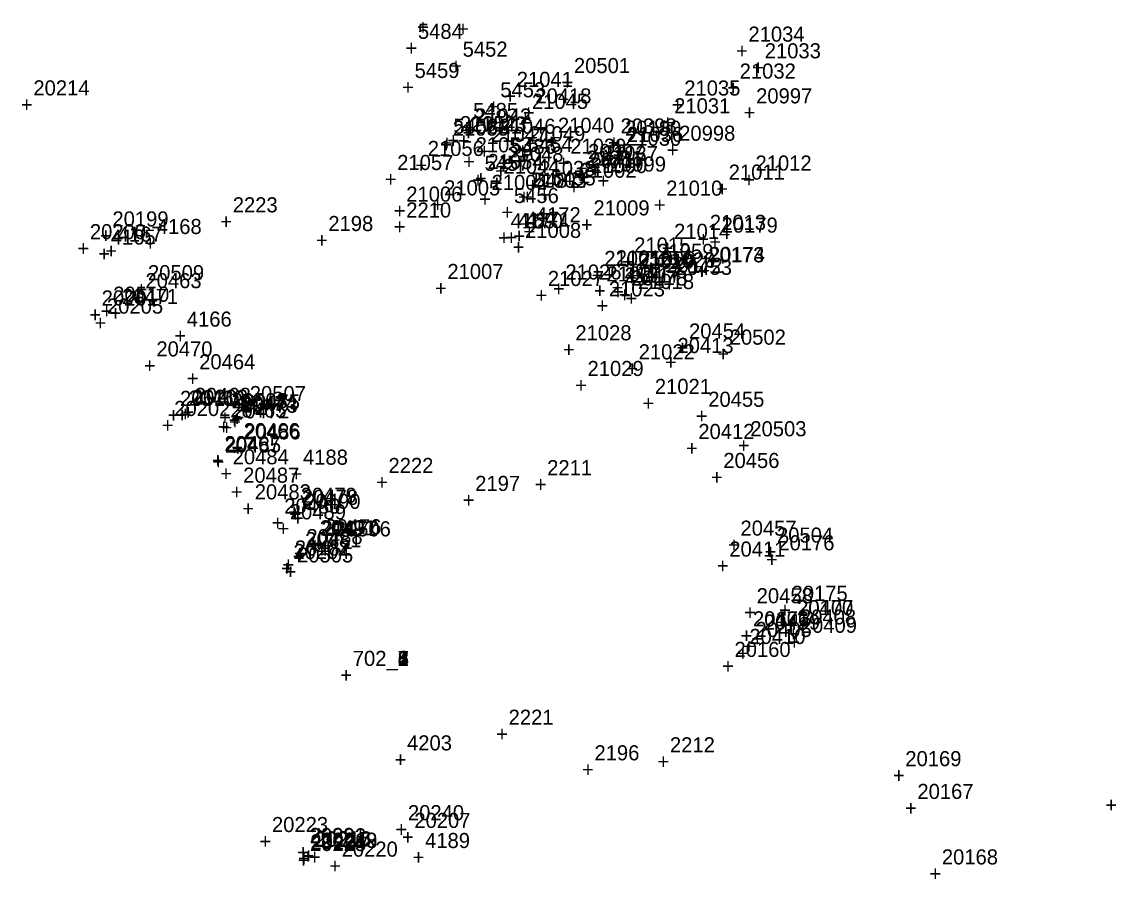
# Model space of a CAD drawing. Extents: x 1036751 to 1042192, y 772604 to 785439.
# Drawn here: x 1041377 to 1041558.2, y 774615.1 to 774757.2 of the extents above; entities that cross this region are included whole.
import ezdxf

# ---------------------------------------------------------------- set-up
doc = ezdxf.new("R2010")
doc.units = 0
for name, color, linetype in [('S_Buildings', 7, 'Continuous'), ('S_Buildings_Attachments', 7, 'Continuous'), ('S_Buildings_SillElevation', 7, 'Continuous'), ('S_Buildings_Steps_Brick', 7, 'Continuous'), ('S_Control_Temp_Traverse', 7, 'Continuous'), ('S_Drainage_CB', 7, 'Continuous'), ('S_Drainage_Culvert_Top', 7, 'Continuous'), ('S_Drainage_Invert', 7, 'Continuous'), ('S_Drainage_Sump', 7, 'Continuous'), ('S_Ground_Elevation', 7, 'Continuous'), ('S_Ground_LevelString', 7, 'Continuous'), ('S_Misc_MiscItems', 7, 'Continuous'), ('S_Property_ConcPad', 7, 'Continuous'), ('S_Property_IronPipeFound', 7, 'Continuous'), ('S_Property_Lawn', 7, 'Continuous'), ('S_Roadway_Centerline', 7, 'Continuous'), ('S_Roadway_Edge_Pavement', 7, 'Continuous'), ('S_Roadway_Edge_TW', 7, 'Continuous'), ('S_Traffic_Post_Conc', 7, 'Continuous'), ('S_Traffic_Sign_DoublePost', 7, 'Continuous'), ('S_Utilities_GuyWire3', 7, 'Continuous'), ('S_Utilities_Pole_Power', 7, 'Continuous'), ('S_Utilities_UG_Sanitary_MH', 7, 'Continuous'), ('S_Utilities_UG_Sanitary_Sewer', 7, 'Continuous'), ('S_Utilities_UG_Water_Shutoff', 7, 'Continuous')]:
    doc.layers.add(name, color=color, linetype=linetype)

msp = doc.modelspace()

# ---------------------------------------------------------------- texts
at = {"layer": 'S_Buildings'}
for s, p in [('20180', (1041476.9, 774738.29)), ('+', (1041474.84, 774735.54)), ('20174', (1041490.78, 774717.38)), ('+', (1041488.71, 774714.63)), ('20201', (1041390.22, 774710.17)), ('+', (1041388.16, 774707.42)), ('20203', (1041405.16, 774693.72)), ('20202', (1041402.24, 774691.86)), ('+', (1041403.1, 774690.97)), ('+', (1041400.17, 774689.11)), ('20204', (1041421.97, 774668.16)), ('+', (1041419.91, 774665.41)), ('20175', (1041504.47, 774661.24)), ('+', (1041502.41, 774658.49)), ('20167', (1041525.31, 774628.42)), ('+', (1041523.24, 774625.67)), ('20207', (1041442, 774623.62)), ('+', (1041439.94, 774620.87)), ('20168', (1041529.36, 774617.57)), ('+', (1041527.3, 774614.82))]:
    msp.add_text(s, height=2.5, dxfattribs=at).set_placement(p)
at = {"layer": 'S_Buildings_Attachments'}
for s, p in [('20398', (1041476.14, 774738.67)), ('+', (1041474.08, 774735.92)), ('20397', (1041470.78, 774734.43)), ('+', (1041468.72, 774731.68)), ('20463', (1041397.47, 774713.04)), ('20471', (1041393.59, 774710.43)), ('+', (1041395.4, 774710.29)), ('+', (1041391.53, 774707.68)), ('20470', (1041399.28, 774701.73)), ('+', (1041397.21, 774698.98)), ('20464', (1041406.37, 774699.6)), ('+', (1041404.31, 774696.85)), ('20469', (1041404.64, 774693.58)), ('20468', (1041405.62, 774694.03)), ('20475', (1041413.75, 774692.95)), ('20465', (1041411.52, 774691.6)), ('20472', (1041412, 774691.47)), ('20474', (1041413.3, 774692.7)), ('20473', (1041413.39, 774692.41)), ('+', (1041402.58, 774690.83)), ('+', (1041403.56, 774691.28)), ('+', (1041411.24, 774689.95)), ('+', (1041411.68, 774690.2)), ('+', (1041409.46, 774688.85)), ('+', (1041409.93, 774688.72)), ('+', (1041411.33, 774689.66)), ('20466', (1041413.74, 774688.19)), ('20486', (1041413.87, 774687.99)), ('20467', (1041410.54, 774686.04)), ('20485', (1041410.63, 774685.81)), ('+', (1041411.68, 774685.44)), ('+', (1041411.81, 774685.24)), ('20484', (1041411.91, 774683.86)), ('+', (1041408.48, 774683.29)), ('+', (1041408.57, 774683.06)), ('+', (1041409.85, 774681.11)), ('20483', (1041415.57, 774678.05)), ('20479', (1041423.18, 774677.48)), ('20478', (1041423.38, 774677.14)), ('+', (1041413.51, 774675.3)), ('20480', (1041420.46, 774675.7)), ('+', (1041421.12, 774674.74)), ('+', (1041421.32, 774674.39)), ('+', (1041418.4, 774672.95)), ('20477', (1041426.65, 774672)), ('20476', (1041427.24, 774672.27)), ('20481', (1041423.93, 774670.13)), ('20482', (1041422.21, 774668.75)), ('+', (1041424.59, 774669.25)), ('+', (1041425.18, 774669.52)), ('+', (1041421.87, 774667.38)), ('+', (1041420.15, 774666))]:
    msp.add_text(s, height=2.5, dxfattribs=at).set_placement(p)
at = {"layer": 'S_Buildings_SillElevation'}
for s, p in [('20501', (1041468.43, 774748.67)), ('+', (1041466.37, 774745.92)), ('20205', (1041391.1, 774708.82)), ('+', (1041389.04, 774706.07)), ('20502', (1041494.23, 774703.68)), ('+', (1041492.17, 774700.93)), ('20503', (1041497.64, 774688.5)), ('+', (1041495.58, 774685.75)), ('20487', (1041413.65, 774680.81)), ('+', (1041411.59, 774678.06)), ('20504', (1041502.06, 774670.89)), ('20176', (1041502.28, 774669.61)), ('+', (1041500, 774668.14)), ('+', (1041500.22, 774666.86)), ('20169', (1041523.31, 774633.85)), ('+', (1041521.25, 774631.1))]:
    msp.add_text(s, height=2.5, dxfattribs=at).set_placement(p)
at = {"layer": 'S_Buildings_Steps_Brick'}
for s, p in [('20490', (1041423.79, 774676.48)), ('20489', (1041421.38, 774674.74)), ('+', (1041421.73, 774673.73)), ('+', (1041419.32, 774671.99)), ('20491', (1041426.33, 774672.09)), ('20488', (1041424.13, 774670.63)), ('+', (1041424.27, 774669.34)), ('+', (1041422.06, 774667.88)), ('20407', (1041505.41, 774658.86)), ('20406', (1041498.09, 774657)), ('20408', (1041505.86, 774657.32)), ('20405', (1041498.51, 774655.25)), ('+', (1041503.35, 774656.11)), ('+', (1041496.03, 774654.25)), ('+', (1041503.8, 774654.57)), ('+', (1041496.45, 774652.5))]:
    msp.add_text(s, height=2.5, dxfattribs=at).set_placement(p)
at = {"layer": 'S_Control_Temp_Traverse'}
for s, p in [('702', (1041431.8, 774650.46)), ('702_7', (1041431.81, 774650.46)), ('702_6', (1041431.81, 774650.46)), ('702_5', (1041431.81, 774650.46)), ('702_4', (1041431.81, 774650.46)), ('702_3', (1041431.81, 774650.46)), ('702_2', (1041431.81, 774650.46)), ('702_1', (1041431.81, 774650.46)), ('702_8', (1041431.81, 774650.46)), ('+', (1041429.74, 774647.71)), ('+', (1041429.74, 774647.71)), ('+', (1041429.74, 774647.71)), ('+', (1041429.74, 774647.71)), ('+', (1041429.74, 774647.71)), ('+', (1041429.74, 774647.71)), ('+', (1041429.74, 774647.71)), ('+', (1041429.74, 774647.71)), ('+', (1041429.74, 774647.71))]:
    msp.add_text(s, height=2.5, dxfattribs=at).set_placement(p)
at = {"layer": 'S_Drainage_CB'}
for s, p in [('20216', (1041425.57, 774620.56)), ('+', (1041423.51, 774617.81))]:
    msp.add_text(s, height=2.5, dxfattribs=at).set_placement(p)
at = {"layer": 'S_Drainage_Culvert_Top'}
for s, p in [('20223', (1041418.42, 774622.93)), ('20222', (1041424.71, 774621.06)), ('+', (1041416.36, 774620.18)), ('20225', (1041424.72, 774619.79)), ('20219', (1041426.57, 774620.34)), ('20220', (1041429.96, 774618.86)), ('+', (1041422.65, 774618.31)), ('+', (1041424.51, 774617.59)), ('+', (1041422.66, 774617.04)), ('+', (1041427.9, 774616.11))]:
    msp.add_text(s, height=2.5, dxfattribs=at).set_placement(p)
at = {"layer": 'S_Drainage_Invert'}
for s, p in [('20221', (1041424.65, 774621.12)), ('20224', (1041424.79, 774620.08)), ('20218', (1041426.58, 774620.3)), ('+', (1041422.59, 774618.37)), ('+', (1041422.73, 774617.33)), ('+', (1041424.52, 774617.55))]:
    msp.add_text(s, height=2.5, dxfattribs=at).set_placement(p)
at = {"layer": 'S_Drainage_Sump'}
for s, p in [('20217', (1041425.46, 774620.47)), ('+', (1041423.4, 774617.72))]:
    msp.add_text(s, height=2.5, dxfattribs=at).set_placement(p)
at = {"layer": 'S_Ground_Elevation'}
for s, p in [('21034', (1041497.33, 774753.88)), ('21033', (1041500.03, 774751.12)), ('+', (1041495.27, 774751.13)), ('21032', (1041495.88, 774747.76)), ('+', (1041497.97, 774748.37)), ('20418', (1041462.03, 774743.64)), ('21035', (1041486.7, 774744.95)), ('+', (1041493.82, 774745.01)), ('21031', (1041485.03, 774742)), ('+', (1041459.97, 774740.89)), ('+', (1041484.64, 774742.2)), ('+', (1041482.97, 774739.25)), ('21030', (1041476.9, 774736.63)), ('21036', (1041477.21, 774737.28)), ('20417', (1041470.99, 774732.93)), ('21037', (1041473.04, 774734.1)), ('+', (1041474.84, 774733.88)), ('+', (1041475.15, 774734.53)), ('+', (1041468.93, 774730.18)), ('+', (1041470.98, 774731.35)), ('20509', (1041397.89, 774714.36)), ('+', (1041395.83, 774711.61)), ('20510', (1041392.12, 774710.79)), ('+', (1041390.06, 774708.04)), ('20511', (1041403.2, 774693.53)), ('20508', (1041411.73, 774693.15)), ('20507', (1041414.75, 774694.33)), ('+', (1041412.69, 774691.58)), ('+', (1041401.14, 774690.78)), ('+', (1041409.67, 774690.4)), ('20506', (1041428.81, 774671.92)), ('20505', (1041422.58, 774667.6)), ('+', (1041426.75, 774669.17)), ('+', (1041420.52, 774664.85))]:
    msp.add_text(s, height=2.5, dxfattribs=at).set_placement(p)
at = {"layer": 'S_Ground_LevelString'}
for s, p in [('+', (1041442.47, 774755.06)), ('5484', (1041442.59, 774754.34)), ('+', (1041449.09, 774754.76)), ('+', (1041440.53, 774751.59)), ('5452', (1041450, 774751.39)), ('5459', (1041442.04, 774747.86)), ('+', (1041447.94, 774748.64)), ('21041', (1041458.96, 774746.38)), ('+', (1041439.98, 774745.11)), ('5453', (1041456.23, 774744.66)), ('+', (1041456.89, 774743.63)), ('21045', (1041461.48, 774742.74)), ('5485', (1041451.74, 774741.23)), ('21042', (1041452.06, 774740.31)), ('+', (1041454.17, 774741.91)), ('21055', (1041448.37, 774738.31)), ('5458', (1041448.48, 774738.63)), ('21052', (1041449.54, 774739.05)), ('21043', (1041451.29, 774738.99)), ('21046', (1041456.09, 774738.62)), ('+', (1041459.42, 774739.99)), ('21040', (1041465.78, 774738.78)), ('+', (1041449.68, 774738.48)), ('+', (1041450, 774737.56)), ('21047', (1041454.69, 774737.26)), ('21049', (1041461.01, 774737.37)), ('21056', (1041444.22, 774734.94)), ('+', (1041446.31, 774735.56)), ('+', (1041446.42, 774735.88)), ('+', (1041447.48, 774736.3)), ('+', (1041449.23, 774736.24)), ('21053', (1041452.15, 774735.54)), ('+', (1041454.03, 774735.87)), ('5486', (1041458, 774735.29)), ('5454', (1041460.75, 774735.61)), ('+', (1041463.72, 774736.03)), ('21039', (1041467.82, 774735.31)), ('+', (1041452.63, 774734.51)), ('21054', (1041454.1, 774732.77)), ('21048', (1041457.41, 774733.99)), ('+', (1041458.95, 774734.62)), ('21057', (1041439.16, 774732.61)), ('+', (1041442.16, 774732.19)), ('+', (1041450.08, 774732.79)), ('5457', (1041453.63, 774732.48)), ('+', (1041455.94, 774732.54)), ('21044', (1041456.75, 774731.99)), ('+', (1041458.69, 774732.86)), ('21038', (1041462.7, 774731.62)), ('+', (1041465.76, 774732.56)), ('21002', (1041469.51, 774731.33)), ('21011', (1041494.06, 774731.02)), ('21012', (1041498.5, 774732.52)), ('+', (1041437.1, 774729.86)), ('+', (1041451.57, 774729.73)), ('+', (1041452.04, 774730.02)), ('21004', (1041454.79, 774729.32)), ('+', (1041455.35, 774731.24)), ('21003', (1041461.26, 774729.68)), ('5487', (1041461.78, 774729.69)), ('5455', (1041464.6, 774730.06)), ('+', (1041496.44, 774729.77)), ('21006', (1041440.66, 774727.38)), ('21005', (1041446.93, 774728.41)), ('+', (1041454.69, 774729.24)), ('+', (1041460.64, 774728.87)), ('+', (1041467.45, 774728.58)), ('21010', (1041483.71, 774728.36)), ('+', (1041492, 774728.27)), ('+', (1041452.73, 774726.57)), ('5456', (1041458.49, 774727.14)), ('+', (1041459.19, 774726.93)), ('+', (1041459.72, 774726.94)), ('+', (1041462.54, 774727.31)), ('+', (1041438.59, 774724.63)), ('+', (1041444.87, 774725.66)), ('+', (1041456.43, 774724.39)), ('21009', (1041471.66, 774725.09)), ('+', (1041481.65, 774725.61)), ('+', (1041469.6, 774722.34)), ('21008', (1041460.33, 774721.37)), ('+', (1041458.27, 774718.62)), ('21025', (1041473.46, 774716.71)), ('21058', (1041479.26, 774716.66)), ('21059', (1041482.24, 774717.89)), ('+', (1041480.18, 774715.14)), ('21007', (1041447.47, 774714.56)), ('21027', (1041464.11, 774713.4)), ('21026', (1041467.01, 774714.47)), ('+', (1041471.39, 774713.96)), ('21024', (1041473.81, 774714.15)), ('+', (1041477.2, 774713.91)), ('+', (1041445.41, 774711.81)), ('+', (1041464.94, 774711.72)), ('21023', (1041474.21, 774711.67)), ('+', (1041462.05, 774710.65)), ('+', (1041471.75, 774711.4)), ('+', (1041472.15, 774708.92)), ('21028', (1041468.67, 774704.4)), ('20413', (1041485.57, 774702.29)), ('+', (1041466.61, 774701.65)), ('21022', (1041479.15, 774701.24)), ('21029', (1041470.68, 774698.49)), ('+', (1041483.51, 774699.54)), ('+', (1041477.09, 774698.49)), ('+', (1041468.62, 774695.74)), ('21021', (1041481.83, 774695.51)), ('+', (1041479.77, 774692.76)), ('20412', (1041489.03, 774688.05)), ('+', (1041486.97, 774685.3)), ('20411', (1041494.16, 774668.57)), ('+', (1041492.1, 774665.82)), ('20409', (1041506, 774655.94)), ('20410', (1041497.48, 774654.09)), ('+', (1041503.94, 774653.19)), ('+', (1041495.42, 774651.34))]:
    msp.add_text(s, height=2.5, dxfattribs=at).set_placement(p)
at = {"layer": 'S_Misc_MiscItems'}
for s, p in [('4203', (1041440.79, 774636.46)), ('+', (1041438.73, 774633.71))]:
    msp.add_text(s, height=2.5, dxfattribs=at).set_placement(p)
at = {"layer": 'S_Property_ConcPad'}
for s, p in [('20173', (1041490.67, 774717.32)), ('20172', (1041483.75, 774715.58)), ('+', (1041488.61, 774714.57)), ('+', (1041481.69, 774712.83)), ('20170', (1041505.38, 774658.87)), ('20171', (1041498.08, 774657.01)), ('+', (1041503.32, 774656.12)), ('+', (1041496.01, 774654.26))]:
    msp.add_text(s, height=2.5, dxfattribs=at).set_placement(p)
at = {"layer": 'S_Property_IronPipeFound'}
for s, p in [('20214', (1041378.91, 774744.97)), ('+', (1041376.84, 774742.22)), ('20160', (1041495.02, 774651.95)), ('+', (1041492.96, 774649.2)), ('20240', (1041440.94, 774624.9)), ('+', (1041438.88, 774622.15))]:
    msp.add_text(s, height=2.5, dxfattribs=at).set_placement(p)
at = {"layer": 'S_Property_Lawn'}
msp.add_text('+', height=2.5, dxfattribs=at).set_placement((1041556.43, 774626.2))
at = {"layer": 'S_Roadway_Centerline'}
for s, p in [('2198', (1041427.76, 774722.5)), ('+', (1041425.7, 774719.75)), ('2197', (1041452.08, 774679.45)), ('+', (1041450.02, 774676.7)), ('2196', (1041471.83, 774634.82)), ('+', (1041469.77, 774632.07))]:
    msp.add_text(s, height=2.5, dxfattribs=at).set_placement(p)
at = {"layer": 'S_Roadway_Edge_Pavement'}
for s, p in [('20997', (1041498.6, 774743.65)), ('+', (1041496.53, 774740.9)), ('20998', (1041485.86, 774737.46)), ('21001', (1041470.51, 774733.32)), ('+', (1041483.8, 774734.71)), ('21000', (1041471.25, 774732.11)), ('20999', (1041474.38, 774732.35)), ('+', (1041468.45, 774730.57)), ('+', (1041472.32, 774729.6)), ('+', (1041469.19, 774729.36)), ('21013', (1041490.94, 774722.69)), ('21014', (1041485.02, 774721.21)), ('21015', (1041478.41, 774718.94)), ('+', (1041488.87, 774719.94)), ('21016', (1041475.36, 774716.81)), ('21020', (1041482.55, 774716.47)), ('+', (1041482.96, 774718.46)), ('+', (1041476.35, 774716.19)), ('21019', (1041479.09, 774716.26)), ('+', (1041473.3, 774714.06)), ('21017', (1041476.83, 774713.97)), ('+', (1041477.03, 774713.51)), ('21018', (1041479.03, 774712.89)), ('+', (1041480.49, 774713.72)), ('+', (1041474.77, 774711.22)), ('+', (1041476.97, 774710.14))]:
    msp.add_text(s, height=2.5, dxfattribs=at).set_placement(p)
at = {"layer": 'S_Roadway_Edge_TW'}
for s, p in [('2223', (1041411.93, 774725.6)), ('2210', (1041440.66, 774724.74)), ('+', (1041409.87, 774722.85)), ('+', (1041438.6, 774721.99)), ('2222', (1041437.72, 774682.42)), ('2211', (1041464, 774682.06)), ('+', (1041435.66, 774679.67)), ('+', (1041461.94, 774679.31)), ('2221', (1041457.61, 774640.71)), ('+', (1041455.54, 774637.96)), ('2212', (1041484.33, 774636.14)), ('+', (1041482.27, 774633.39))]:
    msp.add_text(s, height=2.5, dxfattribs=at).set_placement(p)
at = {"layer": 'S_Traffic_Post_Conc'}
for s, p in [('20453', (1041485.3, 774715.25)), ('+', (1041483.24, 774712.5)), ('20454', (1041487.49, 774704.69)), ('+', (1041485.43, 774701.94)), ('20455', (1041490.67, 774693.39)), ('+', (1041488.6, 774690.64)), ('20456', (1041493.17, 774683.25)), ('+', (1041491.11, 774680.5)), ('20457', (1041496.01, 774672.04)), ('+', (1041493.95, 774669.29)), ('20458', (1041498.69, 774660.84)), ('+', (1041496.62, 774658.09)), ('20459', (1041499.89, 774656.49)), ('+', (1041497.83, 774653.74))]:
    msp.add_text(s, height=2.5, dxfattribs=at).set_placement(p)
at = {"layer": 'S_Traffic_Sign_DoublePost'}
for s, p in [('20199', (1041392, 774723.26)), ('20200', (1041388.27, 774721.15)), ('+', (1041389.94, 774720.51)), ('+', (1041386.21, 774718.4))]:
    msp.add_text(s, height=2.5, dxfattribs=at).set_placement(p)
at = {"layer": 'S_Utilities_GuyWire3'}
for s, p in [('20179', (1041492.89, 774722.24)), ('+', (1041490.83, 774719.49))]:
    msp.add_text(s, height=2.5, dxfattribs=at).set_placement(p)
at = {"layer": 'S_Utilities_Pole_Power'}
for s, p in [('20177', (1041476.74, 774714.66)), ('20178', (1041477.9, 774713.48)), ('+', (1041474.68, 774711.91)), ('+', (1041475.84, 774710.73))]:
    msp.add_text(s, height=2.5, dxfattribs=at).set_placement(p)
at = {"layer": 'S_Utilities_UG_Sanitary_MH'}
for s, p in [('4170', (1041459.15, 774722.97)), ('4165', (1041391.72, 774720.26)), ('+', (1041457.09, 774720.22)), ('+', (1041389.66, 774717.51)), ('4166', (1041404.32, 774706.67)), ('+', (1041402.26, 774703.92))]:
    msp.add_text(s, height=2.5, dxfattribs=at).set_placement(p)
at = {"layer": 'S_Utilities_UG_Sanitary_Sewer'}
for s, p in [('4172', (1041462.12, 774723.95)), ('4168', (1041399.35, 774722.01)), ('4169', (1041457.94, 774722.93)), ('4171', (1041460.45, 774723.21)), ('4167', (1041392.87, 774720.74)), ('+', (1041460.06, 774721.2)), ('+', (1041397.29, 774719.26)), ('+', (1041455.88, 774720.18)), ('+', (1041458.39, 774720.46)), ('+', (1041390.81, 774717.99))]:
    msp.add_text(s, height=2.5, dxfattribs=at).set_placement(p)
at = {"layer": 'S_Utilities_UG_Water_Shutoff'}
for s, p in [('4188', (1041423.56, 774683.79)), ('+', (1041421.5, 774681.04)), ('4189', (1041443.78, 774620.29)), ('+', (1041441.72, 774617.54))]:
    msp.add_text(s, height=2.5, dxfattribs=at).set_placement(p)

doc.saveas('drawing.dxf')
